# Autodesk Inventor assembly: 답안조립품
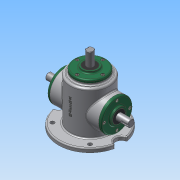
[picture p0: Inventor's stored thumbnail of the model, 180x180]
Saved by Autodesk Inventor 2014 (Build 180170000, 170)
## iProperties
Created: 2018-04
Part Number: 답안조립품
Document SubType Name: Assembly
Designer: NET
Author: NET
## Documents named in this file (16)
- C:\Users\NET\Desktop\480407V1014\답안조립품.iam
- C:\Users\NET\Desktop\480407V1014\본체.ipt
- C:\Users\NET\Desktop\480407V1014\서브 축.ipt
- 서브 축.ipt
- C:\Users\NET\Desktop\480407V1014\메인 축.ipt
- 메인 축.ipt
- C:\Users\NET\Desktop\480407V1014\키 5x5.ipt
- C:\Users\NET\Desktop\480407V1014\베어링 6203.ipt
- C:\Users\NET\Desktop\480407V1014\커버.ipt
- C:\Users\NET\Desktop\480407V1014\오일 실.ipt
- 오일 실.ipt
- C:\Users\NET\Desktop\480407V1014\메인 베벨기어.ipt
- C:\Users\NET\Desktop\480407V1014\키 4x4.ipt
- C:\Users\NET\Desktop\480407V1014\서브 베벨기어.ipt
- C:\Users\NET\Desktop\480407V1014\볼트 M4.ipt
- 볼트 M4.ipt
